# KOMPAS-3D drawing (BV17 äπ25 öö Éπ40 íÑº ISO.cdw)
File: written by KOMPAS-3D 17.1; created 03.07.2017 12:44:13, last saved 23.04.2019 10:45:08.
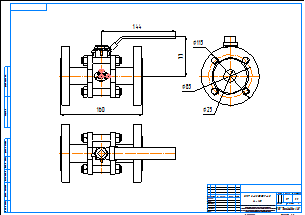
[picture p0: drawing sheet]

Sheet 1: A2, landscape

Title block, sheet 1: name: BV17 Ду25 ФФ Ру40 / без ISO; material: Внимание! Данный продукт является объектом авторского права ООО «Торговый Дом АДЛ». / Запрещается изменение, копирование, распространение / (в том числе путем копирования на другие сайты и ресурсы в Интернете) / или любое иное использование информации и объектов без предварительного / согласия правообладателя (ООО «Торговый Дом АДЛ»).; mass: 1,7; sheets: 1; organisation: ООО "Торговый дом АДЛ"; sheet format: A2; stored path: C:\Users\kka\KOMPAS_Work\!Trash\СС02 СС03 ФФ Смотровые стекла\СС01.cdw

Views: Спереди 1, Проекционный вид 2, Проекционный вид 3
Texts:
  Klimkovich
  ADL
Dimensions and other numbers on the sheet: 160; 144; 77; 85; 115; 25; 1:1; 1; 1,7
